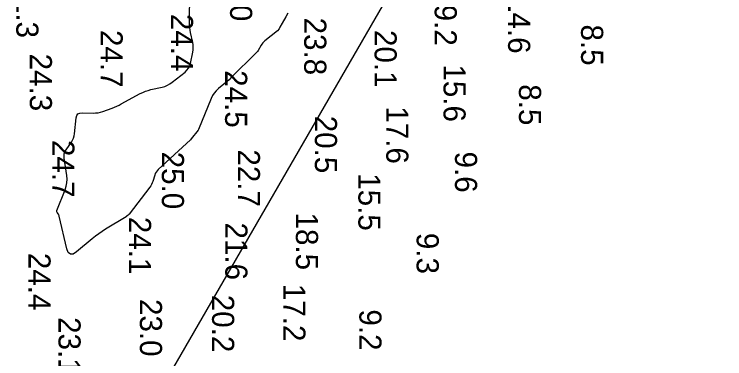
# Model space of a CAD drawing. Extents: x 1178573 to 1187098, y 693282 to 751751.
# Drawn here: x 1182767.3 to 1183169, y 746025.5 to 746220.2 of the extents above; entities that cross this region are included whole.
import ezdxf

# ---------------------------------------------------------------- set-up
doc = ezdxf.new("R2010")
doc.units = 0
for name, color, linetype in [('G-ANNO-PATT', 7, 'Continuous'), ('V-HYDS-MAJR', 7, 'Continuous'), ('V-HYDS-SOUN', 7, 'Continuous')]:
    doc.layers.add(name, color=color, linetype=linetype)

msp = doc.modelspace()

# ---------------------------------------------------------------- linework, layer by layer
at = {"layer": 'G-ANNO-PATT'}
msp.add_line((1182755.92, 745845.24), (1184123.8, 748210.03), dxfattribs=at)
msp.add_lwpolyline([(1182922.05, 746220.88), (1182920.83, 746218.84), (1182918.85, 746215.22), (1182917.43, 746212.92), (1182917.17, 746211.95), (1182916.14, 746210.87), (1182908.97, 746205.15), (1182908.35, 746204.61), (1182907.79, 746204.02), (1182907.3, 746203.37), (1182906.87, 746202.67), (1182905.26, 746199.78), (1182904.8, 746199.13), (1182904.24, 746198.64), (1182889.86, 746184.2), (1182888.9, 746183.22), (1182882.84, 746178.21), (1182881.55, 746177), (1182880.44, 746175.67), (1182879.49, 746174.21), (1182878.73, 746172.62), (1182871.5, 746155.06), (1182871.31, 746154.74), (1182867.41, 746149.8), (1182866.95, 746149.28), (1182848.7, 746132.41), (1182848.06, 746131.74), (1182847.53, 746131.01), (1182847.1, 746130.21), (1182846.78, 746129.35), (1182845.68, 746125.77), (1182845.37, 746124.89), (1182844.99, 746124.05), (1182844.53, 746123.26), (1182844, 746122.5), (1182832.26, 746107.25), (1182832.14, 746107.11), (1182832.02, 746106.97), (1182831.88, 746106.84), (1182831.74, 746106.72), (1182831.17, 746106.24), (1182831.03, 746106.13), (1182830.88, 746106.02), (1182830.72, 746105.91), (1182830.57, 746105.81), (1182819.02, 746098.69), (1182817.07, 746097.43), (1182815.16, 746096.12), (1182813.3, 746094.73), (1182811.49, 746093.28), (1182802.54, 746085.85), (1182800.63, 746084.67), (1182799.1, 746084.58), (1182797.93, 746085.58), (1182797.13, 746087.67), (1182792.85, 746106.05), (1182792.76, 746106.34), (1182792.65, 746106.63), (1182792.51, 746106.91), (1182792.35, 746107.17), (1182791.63, 746108.19), (1182791.49, 746108.46), (1182791.42, 746108.73), (1182791.42, 746109), (1182791.5, 746109.29), (1182796.12, 746121), (1182796.75, 746122.96), (1182797.12, 746124.96), (1182797.21, 746126.99), (1182797.04, 746129.05), (1182795.57, 746138.93), (1182795.49, 746140.19), (1182795.65, 746141.4), (1182796.05, 746142.56), (1182796.68, 746143.65), (1182799.66, 746147.94), (1182800.33, 746149.04), (1182800.85, 746150.19), (1182801.22, 746151.41), (1182801.43, 746152.68), (1182802.37, 746161.62), (1182802.7, 746162.93), (1182803.37, 746163.86), (1182804.37, 746164.4), (1182805.71, 746164.55), (1182811.98, 746164.39), (1182813.37, 746164.42), (1182814.75, 746164.58), (1182816.1, 746164.87), (1182817.43, 746165.28), (1182822.72, 746167.2), (1182824.03, 746167.7), (1182825.31, 746168.25), (1182826.58, 746168.85), (1182827.83, 746169.5), (1182838.58, 746175.35), (1182840.03, 746176.07), (1182841.51, 746176.69), (1182843.04, 746177.2), (1182844.6, 746177.61), (1182850.93, 746179.03), (1182852.48, 746179.46), (1182853.94, 746180.06), (1182855.33, 746180.83), (1182856.64, 746181.75), (1182863.89, 746187.5), (1182864.99, 746188.53), (1182865.86, 746189.69), (1182866.52, 746191), (1182866.95, 746192.44), (1182868.28, 746198.7), (1182868.5, 746200.1), (1182868.57, 746201.5), (1182868.49, 746202.89), (1182868.25, 746204.29), (1182867, 746209.86), (1182866.73, 746211.26), (1182866.54, 746212.67), (1182866.43, 746214.09), (1182866.4, 746215.51), (1182866.59, 746232.42)], dxfattribs=at)
at = {"layer": 'V-HYDS-MAJR'}
msp.add_lwpolyline([(1182922.05, 746220.88), (1182920.83, 746218.84), (1182918.85, 746215.22), (1182917.43, 746212.92), (1182917.17, 746211.95), (1182916.14, 746210.87), (1182908.97, 746205.15), (1182908.35, 746204.61), (1182907.79, 746204.02), (1182907.3, 746203.37), (1182906.87, 746202.67), (1182905.26, 746199.78), (1182904.8, 746199.13), (1182904.24, 746198.64), (1182889.86, 746184.2), (1182888.9, 746183.22), (1182882.84, 746178.21), (1182881.55, 746177), (1182880.44, 746175.67), (1182879.49, 746174.21), (1182878.73, 746172.62), (1182871.5, 746155.06), (1182871.31, 746154.74), (1182867.41, 746149.8), (1182866.95, 746149.28), (1182848.7, 746132.41), (1182848.06, 746131.74), (1182847.53, 746131.01), (1182847.1, 746130.21), (1182846.78, 746129.35), (1182845.68, 746125.77), (1182845.37, 746124.89), (1182844.99, 746124.05), (1182844.53, 746123.26), (1182844, 746122.5), (1182832.26, 746107.25), (1182832.14, 746107.11), (1182832.02, 746106.97), (1182831.88, 746106.84), (1182831.74, 746106.72), (1182831.17, 746106.24), (1182831.03, 746106.13), (1182830.88, 746106.02), (1182830.72, 746105.91), (1182830.57, 746105.81), (1182819.02, 746098.69), (1182817.07, 746097.43), (1182815.16, 746096.12), (1182813.3, 746094.73), (1182811.49, 746093.28), (1182802.54, 746085.85), (1182800.63, 746084.67), (1182799.1, 746084.58), (1182797.93, 746085.58), (1182797.13, 746087.67), (1182792.85, 746106.05), (1182792.76, 746106.34), (1182792.65, 746106.63), (1182792.51, 746106.91), (1182792.35, 746107.17), (1182791.63, 746108.19), (1182791.49, 746108.46), (1182791.42, 746108.73), (1182791.42, 746109), (1182791.5, 746109.29), (1182796.12, 746121), (1182796.75, 746122.96), (1182797.12, 746124.96), (1182797.21, 746126.99), (1182797.04, 746129.05), (1182795.57, 746138.93), (1182795.49, 746140.19), (1182795.65, 746141.4), (1182796.05, 746142.56), (1182796.68, 746143.65), (1182799.66, 746147.94), (1182800.33, 746149.04), (1182800.85, 746150.19), (1182801.22, 746151.41), (1182801.43, 746152.68), (1182802.37, 746161.62), (1182802.7, 746162.93), (1182803.37, 746163.86), (1182804.37, 746164.4), (1182805.71, 746164.55), (1182811.98, 746164.39), (1182813.37, 746164.42), (1182814.75, 746164.58), (1182816.1, 746164.87), (1182817.43, 746165.28), (1182822.72, 746167.2), (1182824.03, 746167.7), (1182825.31, 746168.25), (1182826.58, 746168.85), (1182827.83, 746169.5), (1182838.58, 746175.35), (1182840.03, 746176.07), (1182841.51, 746176.69), (1182843.04, 746177.2), (1182844.6, 746177.61), (1182850.93, 746179.03), (1182852.48, 746179.46), (1182853.94, 746180.06), (1182855.33, 746180.83), (1182856.64, 746181.75), (1182863.89, 746187.5), (1182864.99, 746188.53), (1182865.86, 746189.69), (1182866.52, 746191), (1182866.95, 746192.44), (1182868.28, 746198.7), (1182868.5, 746200.1), (1182868.57, 746201.5), (1182868.49, 746202.89), (1182868.25, 746204.29), (1182867, 746209.86), (1182866.73, 746211.26), (1182866.54, 746212.67), (1182866.43, 746214.09), (1182866.4, 746215.51), (1182866.59, 746232.42)], dxfattribs=at)

# ---------------------------------------------------------------- texts
at = {"layer": 'V-HYDS-SOUN'}
for s, p in [('25.0 ', (1182889.36, 746248.76)), ('21.3 ', (1182768.53, 746239.33)), ('19.2 ', (1183005, 746234.93)), ('14.6 ', (1183046.51, 746230.51)), ('24.4 ', (1182855.93, 746220.44)), ('23.8 ', (1182931.27, 746218.33)), ('8.5', (1183087.76, 746214.42)), ('24.7 ', (1182816.17, 746211.32)), ('20.1 ', (1182971.03, 746211.34)), ('24.3 ', (1182776.17, 746197.96)), ('15.6 ', (1183010, 746191.89)), ('24.5 ', (1182886.55, 746188.59)), ('8.5', (1183052.66, 746180.63)), ('17.6 ', (1182977.65, 746168.2)), ('20.5 ', (1182937.3, 746162.87)), ('24.7 ', (1182788.87, 746149.17)), ('25.0 ', (1182850.81, 746142.56)), ('22.7 ', (1182893.76, 746143.83)), ('9.6', (1183016.5, 746142.62)), ('15.5 ', (1182961.88, 746130.36)), ('24.1 ', (1182832.22, 746105.73)), ('18.5 ', (1182926.58, 746108.14)), ('21.6 ', (1182886.67, 746102.52)), ('9.3', (1182994.82, 746096.66)), ('24.4 ', (1182775.39, 746085.37)), ('17.2 ', (1182919.47, 746067.84)), ('20.2 ', (1182879.18, 746061.67)), ('23.0 ', (1182838.38, 746059.29)), ('9.2', (1182962.44, 746053.41)), ('23.1 ', (1182792.36, 746049.04))]:
    msp.add_text(s, height=12.5, rotation=270, dxfattribs=at).set_placement(p)

doc.saveas('drawing.dxf')
